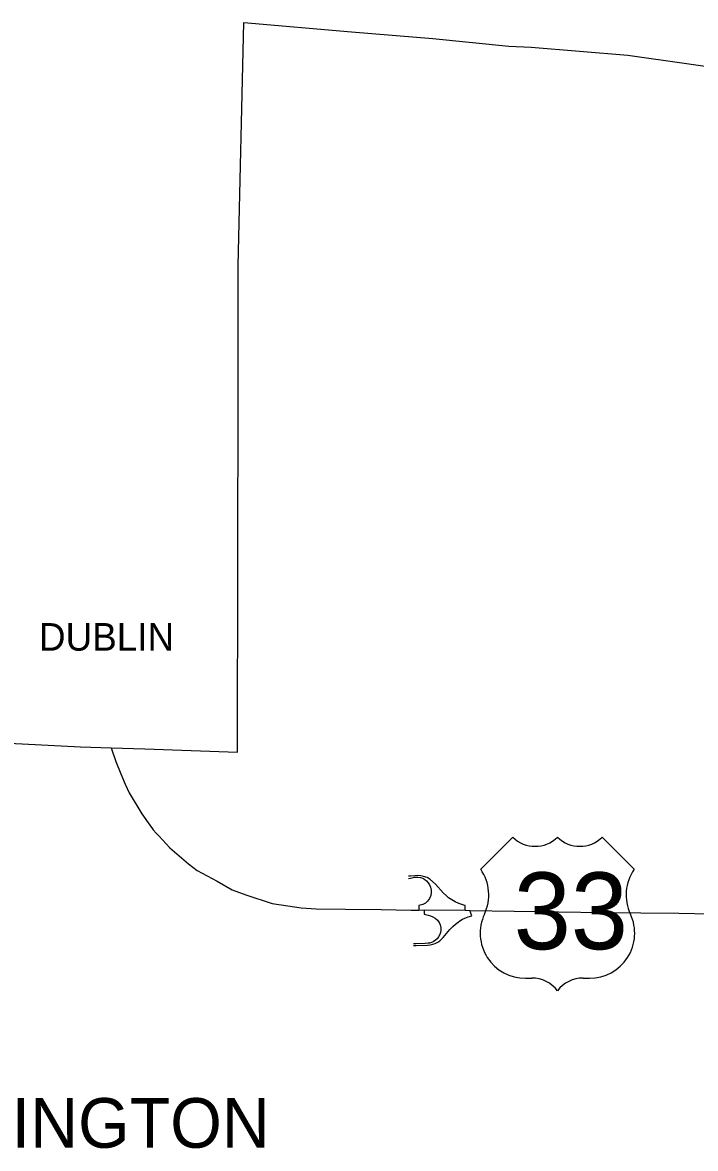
# Model space of a CAD drawing. Extents: x -1146 to -445, y -1283 to -822.
# Drawn here: x -1012.2 to -981.7, y -943.2 to -892.2 of the extents above; entities that cross this region are included whole.
import ezdxf

# ---------------------------------------------------------------- set-up
doc = ezdxf.new("R2010")
doc.units = 0
for name, color, linetype in [('GM_X_Corporation_Text', 7, 'Continuous'), ('GM_X_County', 7, 'Continuous'), ('GM_X_Interchange_Ramps', 7, 'Continuous'), ('GM_X_Township_Text', 7, 'Continuous'), ('GM_X_US_Route', 7, 'Continuous'), ('GM_X_US_Shield', 7, 'Continuous')]:
    doc.layers.add(name, color=color, linetype=linetype)

msp = doc.modelspace()

# ---------------------------------------------------------------- linework, layer by layer
at = {"layer": 'GM_X_County'}
msp.add_lwpolyline([(-1017.275, -924.587), (-1009.61, -924.974), (-1008.223, -925.021), (-1006.705, -925.072), (-1004.601, -925.141), (-1002.503, -925.214), (-1002.503, -925.087), (-1002.461, -908.66), (-1002.471, -903.191), (-1002.216, -892.164), (-997.323, -892.589), (-993.638, -892.888), (-990.204, -893.235), (-989.19, -893.277), (-984.806, -893.649), (-979.482, -894.401)], dxfattribs=at)
at = {"layer": 'GM_X_Interchange_Ramps'}
for points in [[(-992.173, -932.383), (-992.171, -932.167), (-992.245, -932.151), (-992.466, -932.072), (-992.631, -931.992), (-992.788, -931.907), (-992.927, -931.812), (-993.031, -931.728), (-993.168, -931.593), (-993.522, -931.204), (-993.776, -930.968), (-993.901, -930.902), (-994.061, -930.845), (-994.185, -930.819), (-994.318, -930.808), (-994.455, -930.82), (-994.659, -930.832), (-994.746, -930.843)], [(-994.746, -930.942), (-994.653, -930.929), (-994.482, -930.886), (-994.325, -930.876), (-994.206, -930.895), (-994.1, -930.932), (-993.999, -930.989), (-993.925, -931.049), (-993.851, -931.131), (-993.795, -931.221), (-993.75, -931.331), (-993.716, -931.476), (-993.712, -931.574), (-993.735, -931.713), (-993.791, -931.843), (-993.883, -931.972), (-993.981, -932.057), (-994.103, -932.121), (-994.283, -932.166), (-994.274, -932.369)], [(-994.039, -932.366), (-994.041, -932.557), (-993.85, -932.595), (-993.746, -932.631), (-993.647, -932.673), (-993.535, -932.738), (-993.428, -932.835), (-993.357, -932.941), (-993.315, -933.045), (-993.285, -933.17), (-993.283, -933.288), (-993.301, -933.383), (-993.333, -933.485), (-993.382, -933.577), (-993.45, -933.668), (-993.522, -933.739), (-993.63, -933.804), (-993.709, -933.836), (-993.792, -933.864), (-993.859, -933.876), (-993.992, -933.886), (-994.421, -933.902), (-994.52, -933.903)], [(-994.518, -933.975), (-994.399, -933.984), (-993.88, -933.961), (-993.762, -933.946), (-993.639, -933.923), (-993.531, -933.883), (-993.422, -933.826), (-993.332, -933.762), (-993.252, -933.694), (-993.177, -933.615), (-992.869, -933.257), (-992.742, -933.118), (-992.615, -933.007), (-992.498, -932.918), (-992.415, -932.857), (-992.292, -932.788), (-992.188, -932.738), (-992.042, -932.682), (-991.882, -932.639), (-991.959, -932.386)]]:
    msp.add_lwpolyline(points, dxfattribs=at)
at = {"layer": 'GM_X_US_Route'}
for points in [[(-1008.223, -925.021), (-1008.013, -925.641), (-1007.793, -926.204), (-1007.586, -926.67), (-1007.402, -927.06), (-1006.839, -928.014), (-1006.545, -928.427), (-1006.353, -928.692)], [(-1006.353, -928.692), (-1006.322, -928.734), (-1006.18, -928.884)], [(-1006.18, -928.884), (-1006.064, -929.007), (-1005.564, -929.549), (-1004.716, -930.278), (-1004.325, -930.579), (-1003.423, -931.066), (-1002.736, -931.459), (-1002.127, -931.685), (-1000.929, -932.068), (-1000.223, -932.176), (-999.614, -932.265), (-998.937, -932.314), (-997.608, -932.327)], [(-997.608, -932.327), (-995.982, -932.343), (-994.631, -932.379)], [(-994.631, -932.379), (-994.274, -932.369), (-994.039, -932.366), (-992.173, -932.383), (-991.959, -932.386), (-985.939, -932.478), (-982.488, -932.515), (-981.054, -932.538), (-980.61, -932.544)]]:
    msp.add_lwpolyline(points, dxfattribs=at)
at = {"layer": 'GM_X_US_Shield'}
for p, q in [((-990.024, -929.07), (-991.474, -930.52)), ((-984.513, -930.52), (-985.963, -929.07)), ((-989.444, -935.451), (-989.154, -935.451)), ((-986.833, -935.451), (-986.543, -935.451))]:
    msp.add_line(p, q, dxfattribs=at)
for centre, radius, start, end in [((-989.009, -928.034), 1.45, 225.573, 314.427), ((-986.978, -928.034), 1.45, 225.573, 314.427), ((-993.137, -931.685), 2.03, 334.5471, 35.0009), ((-982.85, -931.685), 2.03, 144.9991, 205.4529), ((-989.466, -933.421), 2.03, 154.8319, 270.6383), ((-986.521, -933.421), 2.03, 269.3617, 25.1681), ((-989.154, -936.901), 1.45, 36.8699, 90), ((-986.833, -936.901), 1.45, 90, 143.1301)]:
    msp.add_arc(centre, radius, start, end, dxfattribs=at)

# ---------------------------------------------------------------- texts
at = {"layer": 'GM_X_Corporation_Text'}
msp.add_text('DUBLIN', height=1.25, rotation=0, dxfattribs=at).set_placement((-1011.5, -920.62))
at = {"layer": 'GM_X_Township_Text'}
msp.add_text('WASHINGTON', height=2.25, rotation=0, dxfattribs=at).set_placement((-1021.761, -943.14))
at = {"layer": 'GM_X_US_Shield'}
msp.add_text('33', height=3.4805, dxfattribs=at).set_placement((-989.975, -934.146))

doc.saveas('drawing.dxf')
